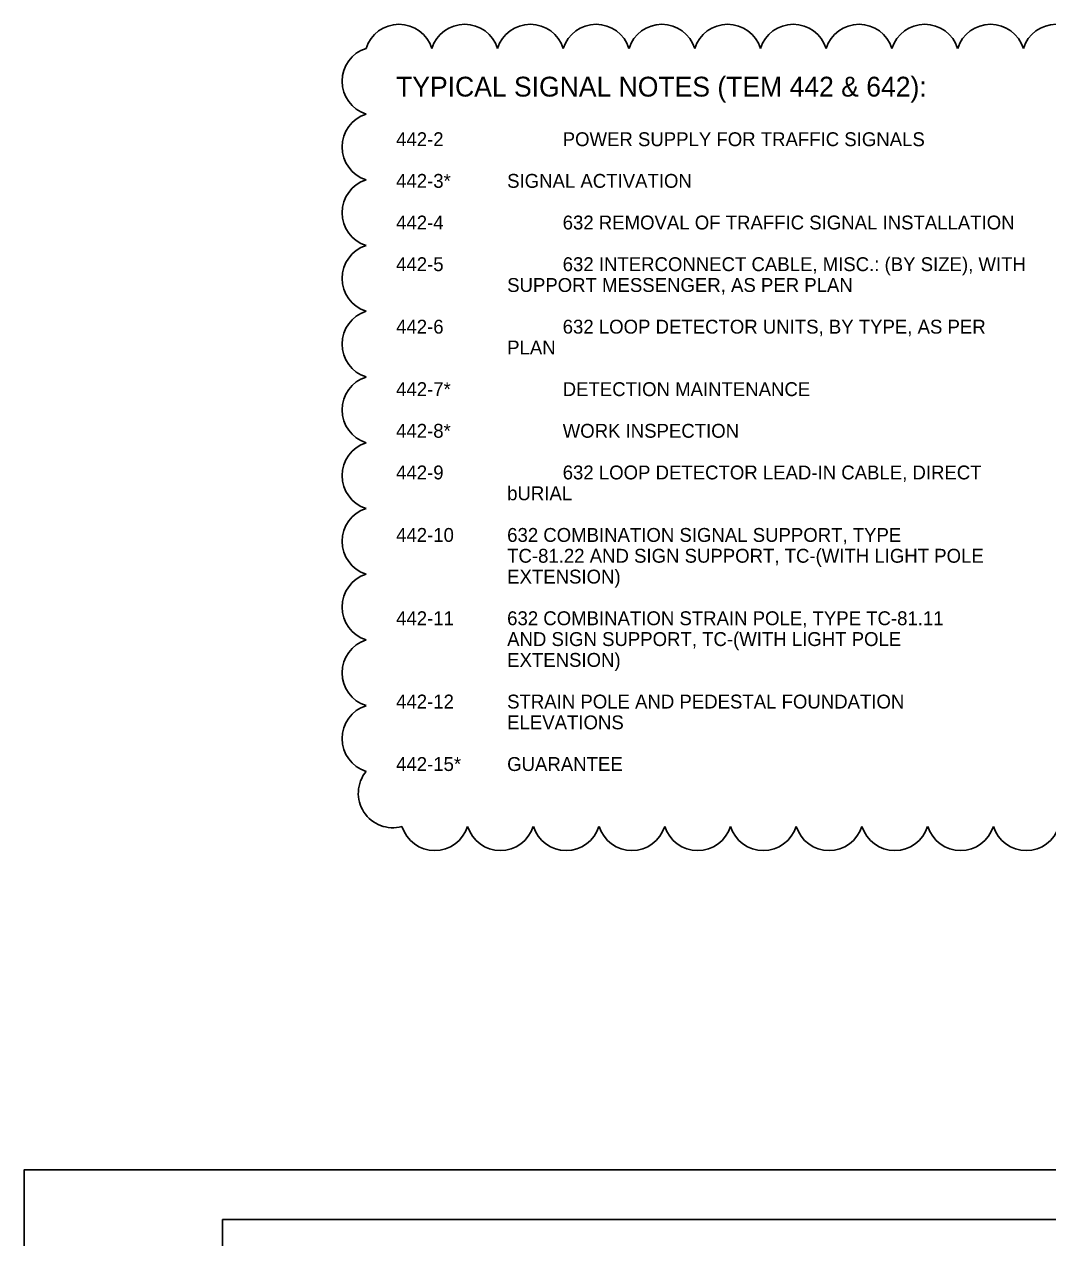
# Model space of a CAD drawing. Extents: x -16 to 109, y -28 to 34.
# Drawn here: x 0 to 10.32, y 21.31 to 33.55 of the extents above; entities that cross this region are included whole.
import ezdxf

# ---------------------------------------------------------------- set-up
doc = ezdxf.new("R2010")
doc.units = 0
for name, color, linetype in [('SC_Scratch1', 7, 'Continuous'), ('SH_Border', 7, 'Continuous'), ('SH_Cut_Line', 7, 'Continuous')]:
    doc.layers.add(name, color=color, linetype=linetype)

msp = doc.modelspace()

# ---------------------------------------------------------------- linework, layer by layer
at = {"layer": 'SC_Scratch1'}
for centre, start, end in [((3.779, 33.203), 17.5, 162.5), ((4.442, 33.203), 17.5, 162.5), ((5.104, 33.203), 17.5, 162.5), ((5.767, 33.203), 17.5, 162.5), ((6.43, 33.203), 17.5, 162.5), ((7.093, 33.203), 17.5, 162.5), ((7.755, 33.203), 17.5, 162.5), ((8.418, 33.203), 17.5, 162.5), ((9.081, 33.203), 17.5, 162.5), ((9.744, 33.203), 17.5, 162.5), ((10.406, 33.203), 17.5, 162.5), ((3.552, 32.976), 107.5, 252.5), ((3.552, 32.313), 107.5, 252.5), ((3.552, 31.65), 107.5, 252.5), ((3.552, 30.988), 107.5, 252.5), ((3.552, 30.325), 107.5, 252.5), ((3.552, 29.662), 107.5, 252.5), ((3.552, 28.999), 107.5, 252.5), ((3.552, 28.337), 107.5, 252.5), ((3.552, 27.674), 107.5, 252.5), ((3.552, 27.011), 107.5, 252.5), ((3.552, 26.348), 107.5, 252.5), ((3.716, 25.796), 140.4948, 285.4948), ((4.14, 25.566), 197.5, 342.5), ((4.802, 25.566), 197.5, 342.5), ((5.465, 25.566), 197.5, 342.5), ((6.128, 25.566), 197.5, 342.5), ((6.791, 25.566), 197.5, 342.5), ((7.453, 25.566), 197.5, 342.5), ((8.116, 25.566), 197.5, 342.5), ((8.779, 25.566), 197.5, 342.5), ((9.442, 25.566), 197.5, 342.5), ((10.104, 25.566), 197.5, 342.5)]:
    msp.add_arc(centre, 0.347, start, end, dxfattribs=at)
at = {"layer": 'SH_Border'}
msp.add_lwpolyline([(2.001, 21.5), (33.501, 21.5), (33.501, 0.5), (2.001, 0.5)], close=True, dxfattribs=at)
at = {"layer": 'SH_Cut_Line'}
msp.add_lwpolyline([(0.001, 0), (34.001, 0), (34.001, 22), (0.001, 22)], close=True, dxfattribs=at)

# ---------------------------------------------------------------- texts
at = {"layer": 'SC_Scratch1'}
for s, height, p in [('TYPICAL SIGNAL NOTES (TEM 442 & 642):', 0.2, (3.75, 32.821)), ('442-2', 0.14, (3.75, 32.321)), ('POWER SUPPLY FOR TRAFFIC SIGNALS ', 0.14, (5.43, 32.321)), ('442-3* ', 0.14, (3.75, 31.901)), ('SIGNAL ACTIVATION', 0.14, (4.87, 31.901)), ('442-4', 0.14, (3.75, 31.481)), ('632 REMOVAL OF TRAFFIC SIGNAL INSTALLATION', 0.14, (5.43, 31.481)), ('442-5', 0.14, (3.75, 31.061)), ('632 INTERCONNECT CABLE, MISC.: (BY SIZE), WITH ', 0.14, (5.43, 31.061)), ('SUPPORT MESSENGER, AS PER PLAN', 0.14, (4.87, 30.851)), ('442-6', 0.14, (3.75, 30.431)), ('632 LOOP DETECTOR UNITS, BY TYPE, AS PER ', 0.14, (5.43, 30.431)), ('PLAN', 0.14, (4.87, 30.221)), ('442-7*', 0.14, (3.75, 29.801)), ('DETECTION MAINTENANCE', 0.14, (5.43, 29.801)), ('442-8*', 0.14, (3.75, 29.381)), ('WORK INSPECTION', 0.14, (5.43, 29.381)), ('442-9', 0.14, (3.75, 28.961)), ('632 LOOP DETECTOR LEAD-IN CABLE, DIRECT ', 0.14, (5.43, 28.961)), ('bURIAL', 0.14, (4.87, 28.751)), ('442-10 ', 0.14, (3.75, 28.331)), ('632 COMBINATION SIGNAL SUPPORT, TYPE ', 0.14, (4.87, 28.331)), ('TC-81.22 AND SIGN SUPPORT, TC-(WITH LIGHT POLE ', 0.14, (4.87, 28.121)), ('EXTENSION)', 0.14, (4.87, 27.911)), ('442-11 ', 0.14, (3.75, 27.491)), ('632 COMBINATION STRAIN POLE, TYPE TC-81.11 ', 0.14, (4.87, 27.491)), ('AND SIGN SUPPORT, TC-(WITH LIGHT POLE ', 0.14, (4.87, 27.281)), ('EXTENSION)', 0.14, (4.87, 27.071)), ('442-12 ', 0.14, (3.75, 26.651)), ('STRAIN POLE AND PEDESTAL FOUNDATION ', 0.14, (4.87, 26.651)), ('ELEVATIONS', 0.14, (4.87, 26.441)), ('442-15*', 0.14, (3.75, 26.021)), ('GUARANTEE', 0.14, (4.87, 26.021))]:
    msp.add_text(s, height=height, dxfattribs=at).set_placement(p)

doc.saveas('drawing.dxf')
